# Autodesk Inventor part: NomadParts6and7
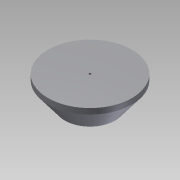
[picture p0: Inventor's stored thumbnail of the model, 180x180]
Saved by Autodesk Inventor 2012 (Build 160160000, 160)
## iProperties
Created: 2012-10
Part Number: NomadParts6and7
Material: Default
Document SubType Name: Modeling
Designer: TechShop Member
Density: 1 g/cm^3
Author: TechShop Member
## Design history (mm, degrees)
sketch "Sketch1"
  geometry: L1 (0, 0)-(0, 63.5); L2 (0, 0)-(56.947, 0); L3 (0, 63.5)-(95.25, 63.5); L4 (95.25, 63.5)-(95.25, 50.8); L5 (95.25, 50.8)-(56.947, 0)
  constraints: 10 end point, 2 perpendicular, 1 parallel, 1 vertical
  dimensions: "d0" = 63.5 distance of L1.start L1.end; "d1" = 56.9468 distance of L1.start L2.end; "d2" = 95.25 distance of L1.end L3.end; "d3" = 12.7 distance of L3.end L4.end
revolve "Revolution1" sketch "Sketch1" stored, may be unused: angle "d4" = 90 deg
sketch "Sketch2"
  geometry: C1 r 95.25 at (0, 0) reference; 1 further point
  constraints: 1 coincident
hole "Hole1" sketch "Sketch2" at (0, 0) diameter "d5" = 5.207; stored, may be unused: countersink angle "d9" = 82 deg, drill point angle "d11" = 118 deg; dims "d6" = 19.05, "d7" = 9.525, "d8" = 6.35, "d10" = 25.4
body "Solid1"
